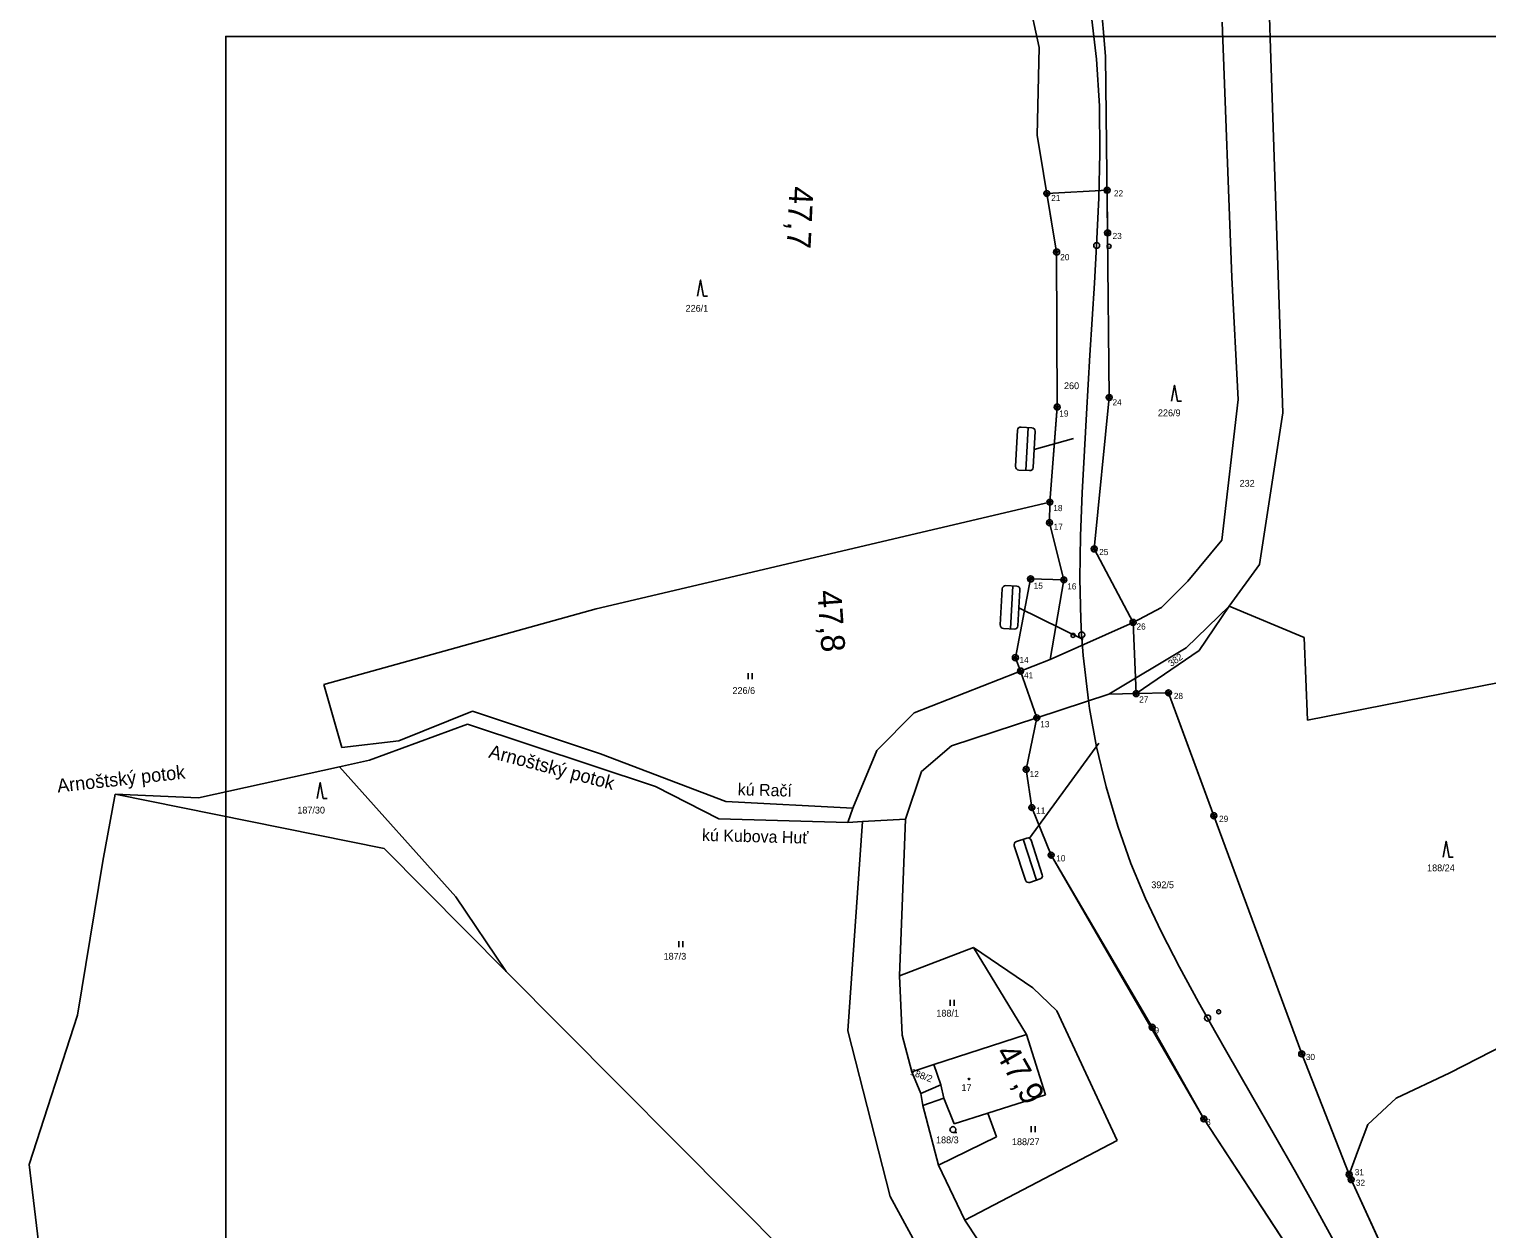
# Model space of a CAD drawing. Extents: x -811039 to -805820, y -1161436 to -1155864.
# Drawn here: x -806908.4 to -806542, y -1157548.8 to -1157247.5 of the extents above; entities that cross this region are included whole.
import ezdxf

# ---------------------------------------------------------------- set-up
doc = ezdxf.new("R2010")
doc.units = 0
for name, color, linetype in [('26 - obvod_stavby', 7, 'Continuous'), ('27 - dočasné zábory', 7, 'Continuous'), ('body', 7, 'Continuous'), ('bublina', 7, 'Continuous'), ('cisla', 7, 'Continuous'), ('Default', 7, 'Continuous'), ('KN_HRANICE', 7, 'Continuous'), ('KN_KULTURY', 7, 'Continuous'), ('KN_PARCELY', 7, 'Continuous'), ('KN_SLUCKY', 7, 'Continuous'), ('kú', 7, 'Continuous'), ('LEGENDA', 7, 'Continuous'), ('SO-Bubliny', 7, 'Continuous'), ('Vrstva 1', 7, 'Continuous'), ('Vrstva 7', 7, 'Continuous')]:
    doc.layers.add(name, color=color, linetype=linetype)

# ---------------------------------------------------------------- blocks, each defined once
blk = doc.blocks.new('306')
at = {"layer": 'Default'}
for p, q in [((-0.5, 1.5), (-0.5, 0)), ((0.5, 0), (0.5, 1.5))]:
    blk.add_line(p, q, dxfattribs=at)
blk = doc.blocks.new('304')
at = {"layer": 'Default'}
blk.add_lwpolyline([(0, 0), (-0.38, 0.1), (-0.65, 0.37), (-0.75, 0.74), (-0.65, 1.11), (-0.38, 1.38), (-0.01, 1.48), (0.36, 1.38), (0.63, 1.11), (0.73, 0.73), (0.63, 0.35), (0.36, 0.08), (-0.02, -0.02), (0.98, -0.02)], dxfattribs=at)
blk = doc.blocks.new('308')
at = {"layer": 'Default'}
blk.add_lwpolyline([(-0.75, 0), (0, 4), (0.75, 0), (1.75, 0)], dxfattribs=at)
blk = doc.blocks.new('402')
at = {"layer": 'Default'}
blk.add_lwpolyline([(0.09, 0.15), (0.18, 0), (0.09, -0.15), (-0.09, -0.15), (-0.18, 0), (-0.09, 0.15), (0.09, 0.15)], dxfattribs=at)
blk = doc.blocks.new('bl_1')
at = {"layer": 'bublina'}
blk.add_line((-675403.21, -978713.71), (-675381.59, -978713.71), dxfattribs=at)
for points in [[(-675401.51, -978710.1), (-675383.29, -978710.1)], [(-675403.21, -978717.27), (-675403.21, -978711.8)], [(-675381.59, -978711.8), (-675381.59, -978717.27)], [(-675383.29, -978718.97), (-675401.51, -978718.97)]]:
    blk.add_lwpolyline(points, dxfattribs=at)
for centre, start, end in [((-675401.51, -978711.8), 90, 180), ((-675383.29, -978711.8), 0, 90), ((-675401.51, -978717.27), 180, 270), ((-675383.29, -978717.27), 270, 0)]:
    blk.add_arc(centre, 1.7, start, end, dxfattribs=at)
blk = doc.blocks.new('bublina_3')
at = {"layer": 'bublina'}
blk.add_blockref('bl_1', (0, 0), dxfattribs=at)

msp = doc.modelspace()

# ---------------------------------------------------------------- linework, layer by layer
at = {"layer": '26 - obvod_stavby'}
for points in [[(-806575.7, -1157578.29), (-806613.16, -1157521.22), (-806626.14, -1157498.2), (-806651.51, -1157454.98), (-806656.38, -1157442.99), (-806657.81, -1157433.42), (-806655.12, -1157420.48), (-806659.21, -1157408.72), (-806660.52, -1157405.37), (-806656.68, -1157385.58), (-806648.34, -1157385.8), (-806651.95, -1157371.45), (-806651.86, -1157366.29), (-806650.04, -1157342.34), (-806650.15, -1157303.45), (-806652.61, -1157288.76), (-806637.47, -1157287.93)], [(-806637.47, -1157287.93), (-806637.33, -1157298.65), (-806636.93, -1157340.01), (-806640.7, -1157378.04), (-806630.94, -1157396.49), (-806630.17, -1157414.39), (-806622.03, -1157414.2), (-806610.63, -1157445.06), (-806588.55, -1157504.89), (-806576.65, -1157535.16), (-806576.13, -1157536.48), (-806569.11, -1157551.76)]]:
    msp.add_lwpolyline(points, dxfattribs=at)
at = {"layer": '27 - dočasné zábory'}
msp.add_lwpolyline([(-806648.34, -1157385.8), (-806656.68, -1157385.58), (-806660.52, -1157405.37), (-806659.21, -1157408.72), (-806655.12, -1157420.48), (-806637.06, -1157414.55), (-806630.17, -1157414.39), (-806630.94, -1157396.49), (-806651.79, -1157405.81)], close=True, dxfattribs=at)
at = {"layer": 'body'}
for p, q in [((-806652.61, -1157288.76), (-806652.61, -1157288.76)), ((-806637.47, -1157287.93), (-806637.47, -1157287.93)), ((-806637.33, -1157298.65), (-806637.33, -1157298.65)), ((-806650.15, -1157303.45), (-806650.15, -1157303.45)), ((-806636.93, -1157340.01), (-806636.93, -1157340.01)), ((-806650.03, -1157342.4), (-806650.03, -1157342.4)), ((-806651.86, -1157366.29), (-806651.86, -1157366.29)), ((-806651.95, -1157371.45), (-806651.95, -1157371.45)), ((-806640.7, -1157378.04), (-806640.7, -1157378.04)), ((-806656.68, -1157385.58), (-806656.68, -1157385.58)), ((-806648.35, -1157385.79), (-806648.35, -1157385.79)), ((-806630.94, -1157396.49), (-806630.94, -1157396.49)), ((-806660.52, -1157405.37), (-806660.52, -1157405.37)), ((-806659.21, -1157408.72), (-806659.21, -1157408.72)), ((-806622.03, -1157414.2), (-806622.03, -1157414.2)), ((-806630.17, -1157414.39), (-806630.17, -1157414.39)), ((-806655.12, -1157420.48), (-806655.12, -1157420.48)), ((-806657.81, -1157433.42), (-806657.81, -1157433.42)), ((-806656.38, -1157442.99), (-806656.38, -1157442.99)), ((-806610.63, -1157445.06), (-806610.63, -1157445.06)), ((-806651.51, -1157454.98), (-806651.51, -1157454.98)), ((-806626.14, -1157498.2), (-806626.14, -1157498.2)), ((-806588.55, -1157504.89), (-806588.55, -1157504.89)), ((-806613.16, -1157521.22), (-806613.16, -1157521.22)), ((-806576.65, -1157535.16), (-806576.65, -1157535.16)), ((-806576.13, -1157536.48), (-806576.13, -1157536.48))]:
    msp.add_line(p, q, dxfattribs=at)
for centre, radius in [((-806652.61, -1157288.76), 0.75), ((-806652.61, -1157288.76), 0.35), ((-806637.47, -1157287.93), 0.75), ((-806637.47, -1157287.93), 0.35), ((-806637.33, -1157298.65), 0.75), ((-806637.33, -1157298.65), 0.35), ((-806650.15, -1157303.45), 0.75), ((-806650.15, -1157303.45), 0.35), ((-806636.93, -1157340.01), 0.75), ((-806636.93, -1157340.01), 0.35), ((-806650.03, -1157342.4), 0.75), ((-806650.03, -1157342.4), 0.35), ((-806651.86, -1157366.29), 0.75), ((-806651.86, -1157366.29), 0.35), ((-806651.95, -1157371.45), 0.75), ((-806651.95, -1157371.45), 0.35), ((-806640.7, -1157378.04), 0.75), ((-806640.7, -1157378.04), 0.35), ((-806656.68, -1157385.58), 0.75), ((-806656.68, -1157385.58), 0.35), ((-806648.34, -1157385.8), 0.75), ((-806648.34, -1157385.8), 0.35), ((-806630.94, -1157396.49), 0.75), ((-806630.94, -1157396.49), 0.35), ((-806660.52, -1157405.37), 0.75), ((-806660.52, -1157405.37), 0.35), ((-806659.21, -1157408.72), 0.75), ((-806659.21, -1157408.72), 0.35), ((-806630.17, -1157414.39), 0.75), ((-806630.17, -1157414.39), 0.35), ((-806622.03, -1157414.2), 0.75), ((-806622.03, -1157414.2), 0.35), ((-806655.12, -1157420.48), 0.75), ((-806655.12, -1157420.48), 0.35), ((-806657.81, -1157433.42), 0.75), ((-806657.81, -1157433.42), 0.35), ((-806656.38, -1157442.99), 0.75), ((-806656.38, -1157442.99), 0.35), ((-806610.63, -1157445.06), 0.75), ((-806610.63, -1157445.06), 0.35), ((-806651.51, -1157454.98), 0.75), ((-806651.51, -1157454.98), 0.35), ((-806626.14, -1157498.2), 0.75), ((-806626.14, -1157498.2), 0.35), ((-806588.55, -1157504.89), 0.75), ((-806588.55, -1157504.89), 0.35), ((-806613.16, -1157521.22), 0.75), ((-806613.16, -1157521.22), 0.35), ((-806576.65, -1157535.16), 0.75), ((-806576.65, -1157535.16), 0.35), ((-806576.13, -1157536.48), 0.75), ((-806576.13, -1157536.48), 0.35)]:
    msp.add_circle(centre, radius, dxfattribs=at)
at = {"layer": 'KN_HRANICE'}
for p, q in [((-806654.56, -1157252.05), (-806660.37, -1157224.72)), ((-806639.66, -1157233.41), (-806637.89, -1157254.23)), ((-806606.13, -1157309.82), (-806608.57, -1157245.67)), ((-806655.07, -1157274.06), (-806654.56, -1157252.05)), ((-806637.89, -1157254.23), (-806637.33, -1157298.65)), ((-806650.15, -1157303.45), (-806655.07, -1157274.06)), ((-806637.33, -1157298.65), (-806636.93, -1157340.01)), ((-806650.03, -1157342.4), (-806650.15, -1157303.45)), ((-806604.5, -1157340.52), (-806606.13, -1157309.82)), ((-806640.7, -1157378.04), (-806636.93, -1157340.01)), ((-806608.67, -1157375.85), (-806604.5, -1157340.52)), ((-806650.03, -1157342.4), (-806651.86, -1157366.29)), ((-806651.86, -1157366.29), (-806765.83, -1157393.08)), ((-806651.86, -1157366.29), (-806651.95, -1157371.45)), ((-806651.95, -1157371.45), (-806648.34, -1157385.8)), ((-806617.2, -1157386.16), (-806608.67, -1157375.85)), ((-806640.7, -1157378.04), (-806630.94, -1157396.49)), ((-806648.34, -1157385.8), (-806651.79, -1157405.81)), ((-806623.83, -1157392.74), (-806617.2, -1157386.16)), ((-806834.34, -1157412.1), (-806765.83, -1157393.08)), ((-806630.94, -1157396.49), (-806623.83, -1157392.74)), ((-806606.79, -1157392.43), (-806617.61, -1157402.91)), ((-806610.63, -1157398.12), (-806606.79, -1157392.43)), ((-806651.79, -1157405.81), (-806630.94, -1157396.49)), ((-806614.37, -1157403.56), (-806610.63, -1157398.12)), ((-806617.61, -1157402.91), (-806637.06, -1157414.55)), ((-806651.79, -1157405.81), (-806685.99, -1157419.22)), ((-806630.17, -1157414.39), (-806614.37, -1157403.56)), ((-806834.34, -1157412.1), (-806829.81, -1157427.9)), ((-806630.17, -1157414.39), (-806622.03, -1157414.2)), ((-806637.06, -1157414.55), (-806655.12, -1157420.48)), ((-806630.17, -1157414.39), (-806637.06, -1157414.55)), ((-806815.48, -1157426.26), (-806796.95, -1157418.8)), ((-806796.95, -1157418.8), (-806764.75, -1157429.51)), ((-806685.99, -1157419.22), (-806695.37, -1157428.66)), ((-806655.12, -1157420.48), (-806676.59, -1157427.52)), ((-806655.12, -1157420.48), (-806657.81, -1157433.42)), ((-806798.17, -1157422.05), (-806822.87, -1157431.12)), ((-806750.98, -1157437.75), (-806798.17, -1157422.05)), ((-806829.81, -1157427.9), (-806815.48, -1157426.26)), ((-806695.37, -1157428.66), (-806701.33, -1157443.18)), ((-806676.59, -1157427.52), (-806684.12, -1157433.91)), ((-806830.37, -1157432.76), (-806822.87, -1157431.12)), ((-806764.75, -1157429.51), (-806733.25, -1157441.5)), ((-806865.79, -1157440.53), (-806830.37, -1157432.76)), ((-806801.13, -1157465.43), (-806830.37, -1157432.76)), ((-806684.12, -1157433.91), (-806688.11, -1157445.96)), ((-806886.75, -1157439.67), (-806889.83, -1157456.49)), ((-806886.75, -1157439.67), (-806889.83, -1157456.49)), ((-806865.79, -1157440.53), (-806886.75, -1157439.67)), ((-806865.79, -1157440.53), (-806886.75, -1157439.67)), ((-806819.15, -1157453.31), (-806886.75, -1157439.67)), ((-806735.07, -1157445.87), (-806750.98, -1157437.75)), ((-806733.25, -1157441.5), (-806701.33, -1157443.18)), ((-806701.33, -1157443.18), (-806702.63, -1157446.72)), ((-806702.63, -1157446.72), (-806735.07, -1157445.87)), ((-806702.63, -1157446.72), (-806698.91, -1157446.53)), ((-806702.6, -1157499.11), (-806698.91, -1157446.53)), ((-806698.91, -1157446.53), (-806688.11, -1157445.96)), ((-806688.11, -1157445.96), (-806689.64, -1157485.31)), ((-806610.63, -1157445.06), (-806588.55, -1157504.89)), ((-806819.15, -1157453.31), (-806788.47, -1157484.17)), ((-806889.83, -1157456.49), (-806896.19, -1157495.2)), ((-806889.83, -1157456.49), (-806896.19, -1157495.2)), ((-806651.51, -1157454.98), (-806613.16, -1157521.22)), ((-806788.47, -1157484.17), (-806801.13, -1157465.43)), ((-806689.64, -1157485.31), (-806671.05, -1157478.15)), ((-806671.05, -1157478.15), (-806656.1, -1157488.33)), ((-806671.05, -1157478.15), (-806657.74, -1157499.99)), ((-806551.31, -1157509.66), (-806500.38, -1157483.48)), ((-806788.47, -1157484.17), (-806717.39, -1157555.67)), ((-806688.96, -1157500.17), (-806689.64, -1157485.31)), ((-806656.1, -1157488.33), (-806650.14, -1157494.04)), ((-806650.14, -1157494.04), (-806634.97, -1157526.64)), ((-806896.19, -1157495.2), (-806908.37, -1157532.64)), ((-806896.19, -1157495.2), (-806908.37, -1157532.64)), ((-806692.02, -1157540.73), (-806702.6, -1157499.11)), ((-806686.52, -1157509.37), (-806688.96, -1157500.17)), ((-806657.74, -1157499.99), (-806681.05, -1157507.59)), ((-806657.74, -1157499.99), (-806652.91, -1157515.2)), ((-806576.65, -1157535.16), (-806588.55, -1157504.89)), ((-806681.05, -1157507.59), (-806686.52, -1157509.37)), ((-806684.3, -1157514.8), (-806686.52, -1157509.37)), ((-806681.05, -1157507.59), (-806679.23, -1157512.7)), ((-806679.23, -1157512.7), (-806684.3, -1157514.8)), ((-806564.84, -1157516.05), (-806551.31, -1157509.66)), ((-806683.79, -1157517.88), (-806684.3, -1157514.8)), ((-806678.53, -1157516.05), (-806683.79, -1157517.88)), ((-806675.89, -1157522.46), (-806678.53, -1157516.05)), ((-806667.43, -1157519.79), (-806652.91, -1157515.2)), ((-806571.93, -1157522.63), (-806564.84, -1157516.05)), ((-806679.87, -1157532.81), (-806683.79, -1157517.88)), ((-806667.43, -1157519.79), (-806675.89, -1157522.46)), ((-806665.28, -1157525.74), (-806667.43, -1157519.79)), ((-806575.7, -1157578.29), (-806613.16, -1157521.22)), ((-806679.87, -1157532.81), (-806665.28, -1157525.74)), ((-806634.97, -1157526.64), (-806673.26, -1157546.66)), ((-806908.37, -1157532.64), (-806901.12, -1157592.09)), ((-806908.37, -1157532.64), (-806901.12, -1157592.09)), ((-806673.26, -1157546.66), (-806679.87, -1157532.81)), ((-806677.94, -1157566.34), (-806692.02, -1157540.73)), ((-806673.26, -1157546.66), (-806666.54, -1157556.83))]:
    msp.add_line(p, q, dxfattribs=at)
for points in [[(-806622.03, -1157414.2), (-806613.94, -1157436.2), (-806610.63, -1157445.06)], [(-806657.81, -1157433.42), (-806656.38, -1157442.99), (-806651.51, -1157454.98)], [(-806576.65, -1157535.16), (-806574.27, -1157528.84), (-806571.93, -1157522.63)], [(-806562.1, -1157567.03), (-806576.13, -1157536.48), (-806576.65, -1157535.16)]]:
    msp.add_lwpolyline(points, dxfattribs=at)
at = {"layer": 'KN_SLUCKY'}
msp.add_line((-806679.23, -1157512.7), (-806678.53, -1157516.05), dxfattribs=at)
at = {"layer": 'kú'}
for p, q in [((-806596.67, -1157244.46), (-806596.41, -1157252.34)), ((-806596.41, -1157252.34), (-806593.33, -1157343.83)), ((-806593.33, -1157343.83), (-806599.19, -1157381.93)), ((-806599.19, -1157381.93), (-806606.79, -1157392.43)), ((-806606.79, -1157392.43), (-806617.61, -1157402.91)), ((-806606.79, -1157392.43), (-806587.9, -1157400.32)), ((-806617.61, -1157402.91), (-806637.06, -1157414.55)), ((-806587.9, -1157400.32), (-806587.1, -1157421.03)), ((-806587.1, -1157421.03), (-806518.99, -1157407.63)), ((-806637.06, -1157414.55), (-806655.12, -1157420.48)), ((-806655.12, -1157420.48), (-806676.59, -1157427.52)), ((-806798.17, -1157422.05), (-806822.87, -1157431.12)), ((-806750.98, -1157437.75), (-806798.17, -1157422.05)), ((-806676.59, -1157427.52), (-806684.12, -1157433.91)), ((-806830.37, -1157432.76), (-806822.87, -1157431.12)), ((-806865.79, -1157440.53), (-806830.37, -1157432.76)), ((-806684.12, -1157433.91), (-806688.11, -1157445.96)), ((-806735.07, -1157445.87), (-806750.98, -1157437.75)), ((-806702.63, -1157446.72), (-806735.07, -1157445.87)), ((-806702.63, -1157446.72), (-806698.91, -1157446.53)), ((-806698.91, -1157446.53), (-806688.11, -1157445.96))]:
    msp.add_line(p, q, dxfattribs=at)
at = {"layer": 'LEGENDA'}
msp.add_lwpolyline([(-806264.96, -1157669.27), (-806858.96, -1157669.27), (-806858.96, -1157249.27), (-806264.96, -1157249.27)], close=True, dxfattribs=at)
at = {"layer": 'SO-Bubliny'}
for points in [[(-806655.81, -1157353.03), (-806645.91, -1157350.28)], [(-806659.63, -1157392.83), (-806643.49, -1157400.78)], [(-806657.01, -1157450.73), (-806639.57, -1157426.86)]]:
    msp.add_lwpolyline(points, dxfattribs=at)
at = {"layer": 'Vrstva 1'}
for points in [[(-806679.67, -1157153.8), (-806673.71, -1157163), (-806667.83, -1157172.53), (-806662.29, -1157182.29), (-806657.45, -1157191.8), (-806652.95, -1157202.08), (-806649.28, -1157211.94), (-806646.03, -1157222.51), (-806643.53, -1157232.65), (-806641.51, -1157243.64), (-806640.1, -1157255.04), (-806639.38, -1157266.73), (-806639.26, -1157278.63), (-806639.53, -1157289.83), (-806640.09, -1157301.8), (-806640.67, -1157311.27)], [(-806640.67, -1157311.27), (-806641.77, -1157329.36), (-806642.63, -1157344.11), (-806643.15, -1157353.34)], [(-806643.15, -1157353.34), (-806643.71, -1157363.93), (-806644.16, -1157374.75), (-806644.32, -1157385.5), (-806644.06, -1157395.76), (-806643.87, -1157399.37), (-806643.49, -1157404.82), (-806642.16, -1157416.12), (-806641.86, -1157418.13), (-806640.12, -1157427.75), (-806637.74, -1157437.77), (-806634.8, -1157447.69), (-806631.47, -1157457.04), (-806627.79, -1157465.88), (-806623.83, -1157474.27), (-806619.27, -1157483.13), (-806614.48, -1157491.87), (-806610.11, -1157499.58), (-806607.34, -1157504.42)], [(-806607.34, -1157504.42), (-806601.16, -1157515.24), (-806595.38, -1157525.34), (-806590.12, -1157534.53)], [(-806590.12, -1157534.53), (-806584.91, -1157543.77), (-806579.66, -1157553.42), (-806574.64, -1157563.14), (-806569.8, -1157573.22), (-806565.07, -1157584.15), (-806561.54, -1157593.02), (-806557.36, -1157604.53), (-806554.68, -1157612.68), (-806551.66, -1157622.8)]]:
    msp.add_lwpolyline(points, dxfattribs=at)
at = {"layer": 'Vrstva 7'}
for p, q in [((-806636.98, -1157301.96), (-806636.99, -1157302.06)), ((-806646.03, -1157399.7), (-806646.03, -1157399.8)), ((-806609.45, -1157494.27), (-806609.4, -1157494.36))]:
    msp.add_line(p, q, dxfattribs=at)
for centre, radius in [((-806640.09, -1157301.8), 0.75), ((-806636.98, -1157302.01), 0.5), ((-806646.03, -1157399.75), 0.5), ((-806643.85, -1157399.61), 0.75), ((-806609.43, -1157494.32), 0.5), ((-806612.2, -1157495.89), 0.75)]:
    msp.add_circle(centre, radius, dxfattribs=at)

# ---------------------------------------------------------------- block references
at = {"layer": 'KN_KULTURY'}
for name, p in [('308', (-806739.63, -1157314.51)), ('308', (-806620.55, -1157340.91)), ('306', (-806727.18, -1157410.73)), ('308', (-806835.2, -1157440.72)), ('308', (-806552.27, -1157455.48)), ('306', (-806744.63, -1157478.1)), ('306', (-806676.37, -1157492.82)), ('402', (-806672.17, -1157511.2)), ('304', (-806676.21, -1157524.64)), ('306', (-806656.07, -1157524.56))]:
    msp.add_blockref(name, p, dxfattribs=at)
at = {"layer": 'SO-Bubliny', "xscale": 0.49999999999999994}
for p, yscale, rotation in [((-336741.07, -1521615.61), 0.5000000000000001, -93.17273143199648), ((-336744.89, -1521655.41), 0.5000000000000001, -93.17273143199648), ((-236319.77, -1325457.41), 0.49999999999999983, -71.80427705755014)]:
    msp.add_blockref('bublina_3', p, dxfattribs=dict(at, yscale=yscale, rotation=rotation))

# ---------------------------------------------------------------- texts
at = {"layer": 'cisla'}
for s, p in [('21', (-806651.52, -1157290.66)), ('22', (-806635.75, -1157289.48)), ('23', (-806636.09, -1157300.2)), ('20', (-806649.25, -1157305.52)), ('24', (-806636.11, -1157341.98)), ('19', (-806649.48, -1157344.79)), ('18', (-806650.98, -1157368.54)), ('17', (-806650.89, -1157373.24)), ('25', (-806639.46, -1157379.59)), ('15', (-806655.92, -1157388.05)), ('16', (-806647.49, -1157388.22)), ('26', (-806630.08, -1157398.3)), ('14', (-806659.48, -1157406.7)), ('41', (-806658.35, -1157410.55)), ('28', (-806620.7, -1157415.75)), ('27', (-806629.4, -1157416.62)), ('13', (-806654.26, -1157422.83)), ('12', (-806656.93, -1157435.37)), ('11', (-806655.3, -1157444.54)), ('29', (-806609.33, -1157446.61)), ('10', (-806650.25, -1157456.53)), (' 9', (-806626.14, -1157499.75)), ('30', (-806587.53, -1157506.44)), (' 8', (-806613.16, -1157522.77)), ('31', (-806575.23, -1157535.39)), ('32', (-806574.95, -1157538.03))]:
    msp.add_text(s, height=1.552, dxfattribs=at).set_placement(p)
at = {"layer": 'KN_PARCELY'}
for s, p in [('226/1', (-806743.4, -1157318.44)), ('260', (-806648.3, -1157337.9)), ('226/9', (-806624.69, -1157344.71)), ('232', (-806604.17, -1157362.4)), ('226/6', (-806731.62, -1157414.46)), ('187/30', (-806840.98, -1157444.5)), ('188/24', (-806557.05, -1157459.01)), ('392/5', (-806626.36, -1157463.26)), ('187/3', (-806748.93, -1157481.21)), ('188/1', (-806680.38, -1157495.52)), ('17', (-806674.07, -1157514.2)), ('188/3', (-806680.46, -1157527.34)), ('188/27', (-806661.38, -1157527.81))]:
    msp.add_text(s, height=1.7, dxfattribs=at).set_placement(p)
for s, height, rotation, p in [('382', 1.7, 35.18, (-806621.35, -1157407.71)), ('Arnoštský potok', 3.4, 345.322, (-806793.09, -1157430.41)), ('Arnoštský potok', 3.4, 6.303, (-806901.16, -1157439.25)), ('188/2', 1.7, 339.592, (-806687.08, -1157510.09))]:
    msp.add_text(s, height=height, rotation=rotation, dxfattribs=at).set_placement(p)
at = {"layer": 'LEGENDA'}
for s, p in [('kú Račí', (-806730.32, -1157439.91)), ('kú Kubova Huť', (-806739.3, -1157451.38))]:
    msp.add_text(s, height=3, rotation=358.5101, dxfattribs=at).set_placement(p)
at = {"layer": 'Vrstva 7'}
for s, rotation, p in [('47,7', 267.323, (-806717.26, -1157286.86)), ('47,8', 273.9953, (-806710.29, -1157388.57)), ('47,9', 299.5371, (-806665.75, -1157504.62))]:
    msp.add_text(s, height=6, rotation=rotation, dxfattribs=at).set_placement(p)

doc.saveas('drawing.dxf')
